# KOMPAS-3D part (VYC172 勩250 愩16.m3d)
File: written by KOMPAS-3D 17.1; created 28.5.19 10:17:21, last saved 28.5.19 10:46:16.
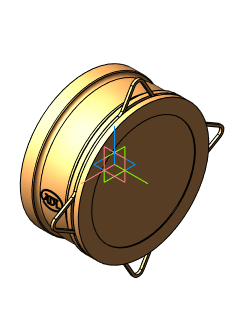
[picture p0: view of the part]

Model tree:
1. Операция без истории:1  (labels: Сталь 20  ГОСТ 1050-2013)

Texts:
  Линейный размер с обрывом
